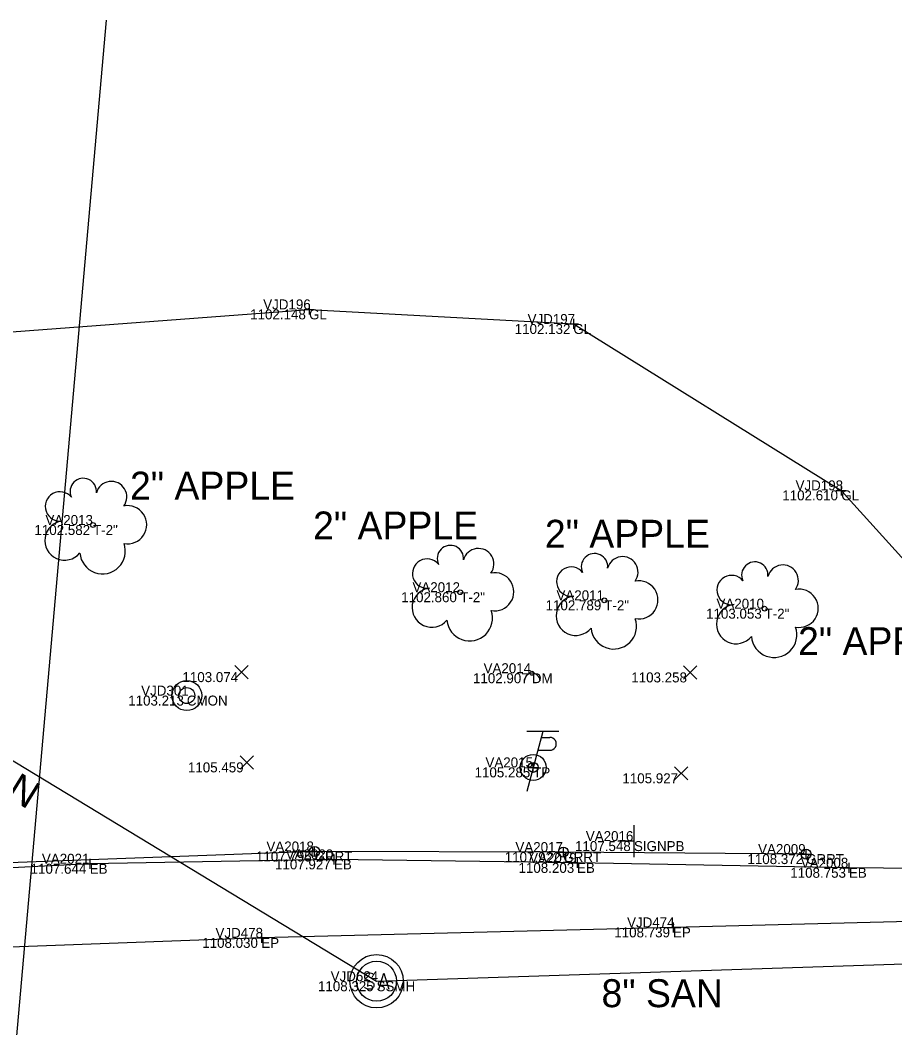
# Model space of a CAD drawing. Extents: x 1629915 to 1630675, y 484401 to 484601.
# Drawn here: x 1630337.7 to 1630425.3, y 484495.4 to 484596.3 of the extents above; entities that cross this region are included whole.
import ezdxf

# ---------------------------------------------------------------- set-up
doc = ezdxf.new("R2010")
doc.units = 0
for name, color, linetype in [('BR_X_Sub_Foot_Object', 7, 'Continuous'), ('Default', 7, 'Continuous'), ('GK_Drainage_Nodes', 7, 'Continuous'), ('PV_X_EOP', 7, 'Continuous'), ('PV_X_Shoulder_Aggregate', 7, 'Continuous'), ('RD_X_GR_Rt', 7, 'Continuous'), ('SC_Scratch2', 7, 'Continuous'), ('SN_X_Public', 7, 'Continuous'), ('SV_X_Mon_Cells_Found', 7, 'Continuous'), ('SV_X_Random_Point', 7, 'Continuous'), ('SV_X_Shot_Marker', 7, 'Continuous'), ('SV_X_Text_Comment', 7, 'Continuous'), ('SV_X_Text_Elevation', 7, 'Continuous'), ('SV_X_Text_Name', 7, 'Continuous'), ('TX_X_20', 7, 'Continuous'), ('UT_X_Gas', 7, 'Continuous'), ('UT_X_Misc_Cells', 7, 'Continuous'), ('UT_X_Sanitary_Cells', 7, 'Continuous'), ('UT_X_Sanitary_Line', 7, 'Continuous'), ('VG_X_Cells', 7, 'Continuous')]:
    doc.layers.add(name, color=color, linetype=linetype)

# ---------------------------------------------------------------- blocks, each defined once
blk = doc.blocks.new('SurveyPointCell')
at = {"layer": 'Default'}
for p, q in [((-0.5, 0), (0.5, 0)), ((0, -0.5), (0, 0.5))]:
    blk.add_line(p, q, dxfattribs=at)
blk.add_circle((0, 0), 0.5, dxfattribs=at)

msp = doc.modelspace()

# ---------------------------------------------------------------- linework, layer by layer
at = {"layer": 'BR_X_Sub_Foot_Object'}
msp.add_line((1630334.98, 484467.23), (1630346.37, 484596.32), dxfattribs=at)
at = {"layer": 'GK_Drainage_Nodes'}
for p, q in [((1630373.42, 484502.09), (1630373.42, 484502.09)), ((1630373.42, 484500.09), (1630373.42, 484500.09)), ((1630373.42, 484500.09), (1630373.42, 484500.09)), ((1630373.42, 484500.09), (1630373.42, 484500.09)), ((1630373.42, 484498.09), (1630373.42, 484498.09))]:
    msp.add_line(p, q, dxfattribs=at)
msp.add_circle((1630373.42, 484500.09), 2, dxfattribs=at)
at = {"layer": 'PV_X_EOP'}
msp.add_lwpolyline([(1630649.54, 484512.34), (1630611.09, 484510.96), (1630568.31, 484509.62), (1630527.92, 484508.55), (1630486.05, 484507.69), (1630439.97, 484506.41), (1630403.1, 484505.48), (1630361.88, 484504.43), (1630301.74, 484502.19)], dxfattribs=at)
at = {"layer": 'PV_X_Shoulder_Aggregate'}
msp.add_lwpolyline([(1630609.29, 484512.62), (1630601.38, 484512.79), (1630594.37, 484513.03), (1630564.66, 484511.71), (1630557.67, 484510.64), (1630535.06, 484510.05), (1630513.96, 484509.73), (1630489.96, 484510.39), (1630468.46, 484511.02), (1630445.09, 484511.2), (1630420.71, 484511.45), (1630393.49, 484511.94), (1630369.15, 484512.29), (1630344.7, 484511.85), (1630320.66, 484510.61), (1630304.12, 484509.44), (1630303.96, 484508.98)], dxfattribs=at)
at = {"layer": 'RD_X_GR_Rt'}
msp.add_lwpolyline([(1630416.42, 484512.82), (1630392.12, 484513.02), (1630367.21, 484513.08), (1630304.23, 484510.75)], dxfattribs=at)
at = {"layer": 'SN_X_Public'}
for p, q in [((1630399.19, 484515.72), (1630399.19, 484512.52)), ((1630399.19, 484514.12), (1630397.59, 484514.12))]:
    msp.add_line(p, q, dxfattribs=at)
at = {"layer": 'SV_X_Mon_Cells_Found'}
for radius in [1.5, 0.8]:
    msp.add_circle((1630354.42, 484528.69), radius, dxfattribs=at)
at = {"layer": 'SV_X_Random_Point'}
for p, q in [((1630359.23, 484530.37), (1630360.57, 484531.7)), ((1630359.23, 484531.7), (1630360.57, 484530.37)), ((1630404.15, 484530.34), (1630405.48, 484531.68)), ((1630404.15, 484531.68), (1630405.48, 484530.34)), ((1630359.75, 484521.33), (1630361.08, 484522.67)), ((1630359.75, 484522.67), (1630361.08, 484521.33)), ((1630403.26, 484520.24), (1630404.59, 484521.57)), ((1630403.26, 484521.57), (1630404.59, 484520.24))]:
    msp.add_line(p, q, dxfattribs=at)
at = {"layer": 'SV_X_Shot_Marker'}
for p, q in [((1630366.16, 484567.36), (1630367.16, 484567.36)), ((1630366.66, 484567.86), (1630366.66, 484566.86)), ((1630366.66, 484567.36), (1630366.66, 484567.36)), ((1630393.12, 484566.4), (1630393.12, 484565.4)), ((1630392.62, 484565.9), (1630393.62, 484565.9)), ((1630393.12, 484565.9), (1630393.12, 484565.9)), ((1630419.45, 484549.24), (1630420.45, 484549.24)), ((1630419.95, 484549.74), (1630419.95, 484548.74)), ((1630419.95, 484549.24), (1630419.95, 484549.24)), ((1630369.15, 484512.79), (1630369.15, 484511.79)), ((1630344.2, 484511.85), (1630345.2, 484511.85)), ((1630344.7, 484512.35), (1630344.7, 484511.35)), ((1630344.7, 484511.85), (1630344.7, 484511.85)), ((1630368.65, 484512.29), (1630369.65, 484512.29)), ((1630369.15, 484512.29), (1630369.15, 484512.29)), ((1630392.99, 484511.94), (1630393.99, 484511.94)), ((1630393.49, 484512.44), (1630393.49, 484511.44)), ((1630393.49, 484511.94), (1630393.49, 484511.94)), ((1630420.71, 484511.95), (1630420.71, 484510.95)), ((1630420.21, 484511.45), (1630421.21, 484511.45)), ((1630420.71, 484511.45), (1630420.71, 484511.45)), ((1630402.6, 484505.48), (1630403.6, 484505.48)), ((1630403.1, 484505.98), (1630403.1, 484504.98)), ((1630403.1, 484505.48), (1630403.1, 484505.48)), ((1630361.38, 484504.43), (1630362.38, 484504.43)), ((1630361.88, 484504.93), (1630361.88, 484503.93)), ((1630361.88, 484504.43), (1630361.88, 484504.43))]:
    msp.add_line(p, q, dxfattribs=at)
at = {"layer": 'UT_X_Gas'}
for points in [[(1630098.57, 484496.17), (1630109.66, 484497.04), (1630113.02, 484497.7), (1630113.95, 484498.76), (1630114.05, 484508.26), (1630114.56, 484509.57), (1630115.81, 484510.86), (1630129.42, 484519.99), (1630159.4, 484536.24), (1630181.58, 484547.98), (1630213.12, 484562.01), (1630240.48, 484573.33), (1630274.59, 484574.58), (1630290.01, 484572.98), (1630327.07, 484564.38), (1630366.66, 484567.36), (1630393.12, 484565.9), (1630419.95, 484549.24), (1630440.64, 484526.36), (1630450.49, 484510.25), (1630452.08, 484508.49), (1630453.28, 484508.55), (1630468.94, 484509.13)], [(1630098.57, 484496.17), (1630109.66, 484497.04), (1630113.02, 484497.7), (1630113.95, 484498.76), (1630114.05, 484508.26), (1630114.56, 484509.57), (1630115.81, 484510.86), (1630129.42, 484519.99), (1630159.4, 484536.24), (1630181.58, 484547.98), (1630213.12, 484562.01), (1630240.48, 484573.33), (1630274.59, 484574.58), (1630290.01, 484572.98), (1630327.07, 484564.38), (1630366.66, 484567.36), (1630393.12, 484565.9), (1630419.95, 484549.24), (1630440.64, 484526.36), (1630450.49, 484510.25), (1630452.08, 484508.49), (1630453.28, 484508.55), (1630494.38, 484510.08)]]:
    msp.add_lwpolyline(points, dxfattribs=at)
at = {"layer": 'UT_X_Misc_Cells'}
for p, q in [((1630390.07, 484525.1), (1630388.46, 484519.1)), ((1630391.67, 484525.1), (1630388.47, 484525.1)), ((1630389.91, 484524.5), (1630390.76, 484524.5)), ((1630389.56, 484523.22), (1630390.76, 484523.22))]:
    msp.add_line(p, q, dxfattribs=at)
for centre, radius in [((1630388.97, 484530.93), 0.2), ((1630389.1, 484521.5), 1.3)]:
    msp.add_circle(centre, radius, dxfattribs=at)
for centre, radius, start, end in [((1630389, 484530.13), 0.8, 2.2454, 182.2454), ((1630390.77, 484523.86), 0.638, 268.8767, 91.1233)]:
    msp.add_arc(centre, radius, start, end, dxfattribs=at)
at = {"layer": 'UT_X_Sanitary_Cells'}
for points in [[(1630373.09, 484500.78), (1630373.06, 484500.81), (1630373.03, 484500.83), (1630372.91, 484500.87), (1630372.77, 484500.89), (1630372.67, 484500.89), (1630372.64, 484500.89), (1630372.47, 484500.86), (1630372.33, 484500.78), (1630372.25, 484500.68), (1630372.22, 484500.58), (1630372.22, 484500.5), (1630372.25, 484500.4), (1630372.35, 484500.32), (1630373.04, 484499.94), (1630373.1, 484499.89), (1630373.13, 484499.84), (1630373.15, 484499.76), (1630373.15, 484499.69), (1630373.14, 484499.61), (1630373.13, 484499.56), (1630373.1, 484499.5), (1630373.08, 484499.45), (1630373.05, 484499.41), (1630373.01, 484499.37), (1630372.98, 484499.35), (1630372.93, 484499.32), (1630372.89, 484499.31), (1630372.77, 484499.29), (1630372.6, 484499.29), (1630372.48, 484499.32), (1630372.32, 484499.41), (1630372.22, 484499.48)], [(1630373.63, 484499.29), (1630374.13, 484500.89), (1630374.63, 484499.29)], [(1630374.5, 484499.67), (1630373.76, 484499.67)]]:
    msp.add_lwpolyline(points, dxfattribs=at)
for radius in [2.67, 2]:
    msp.add_circle((1630373.42, 484500.09), radius, dxfattribs=at)
at = {"layer": 'UT_X_Sanitary_Line'}
msp.add_lwpolyline([(1629930.75, 484483.73), (1630048.13, 484488.31), (1630252.72, 484494.6), (1630261.76, 484567.79), (1630373.42, 484500.09), (1630654.86, 484509.35)], dxfattribs=at)
at = {"layer": 'VG_X_Cells'}
for centre in [(1630345.03, 484545.77), (1630381.79, 484539.04), (1630396.22, 484538.23), (1630412.27, 484537.39)]:
    msp.add_circle(centre, 0.24, dxfattribs=at)
for centre, radius, start, end in [((1630344.05, 484549.13), 1.32, 354.0047, 205.9741), ((1630346.86, 484548.59), 1.55, 323.83, 165.0376), ((1630341.72, 484547.63), 1.47, 39.0625, 279.5412), ((1630348.49, 484545.8), 1.91, 259.1453, 101.4596), ((1630342.18, 484544.22), 1.97, 96.1722, 320.5737), ((1630345.98, 484543.16), 2.28, 184.9476, 19.4572), ((1630380.81, 484542.41), 1.32, 354.0047, 205.9741), ((1630383.62, 484541.87), 1.55, 323.83, 165.0376), ((1630395.24, 484541.6), 1.32, 354.0047, 205.9741), ((1630378.48, 484540.91), 1.47, 39.0625, 279.5412), ((1630398.05, 484541.06), 1.55, 323.83, 165.0376), ((1630411.29, 484540.76), 1.32, 354.0047, 205.9741), ((1630414.1, 484540.22), 1.55, 323.83, 165.0376), ((1630385.25, 484539.08), 1.91, 259.1453, 101.4596), ((1630392.91, 484540.1), 1.47, 39.0625, 279.5412), ((1630399.68, 484538.27), 1.91, 259.1453, 101.4596), ((1630408.96, 484539.26), 1.47, 39.0625, 279.5412), ((1630378.94, 484537.5), 1.97, 96.1722, 320.5737), ((1630415.73, 484537.43), 1.91, 259.1453, 101.4596), ((1630393.37, 484536.68), 1.97, 96.1722, 320.5737), ((1630409.42, 484535.85), 1.97, 96.1722, 320.5737), ((1630382.74, 484536.44), 2.28, 184.9476, 19.4572), ((1630397.17, 484535.63), 2.28, 184.9476, 19.4572), ((1630413.22, 484534.79), 2.28, 184.9476, 19.4572)]:
    msp.add_arc(centre, radius, start, end, dxfattribs=at)

# ---------------------------------------------------------------- block references
at = {"layer": 'SC_Scratch2'}
for p in [(1630389.1, 484521.5), (1630367.21, 484513.08), (1630392.12, 484513.02), (1630416.42, 484512.82)]:
    msp.add_blockref('SurveyPointCell', p, dxfattribs=at)

# ---------------------------------------------------------------- texts
at = {"layer": 'SV_X_Text_Comment'}
for s, p in [('GL', (1630366.66, 484566.36)), ('GL', (1630393.12, 484564.9)), ('GL', (1630419.95, 484548.24)), ('T-2"', (1630345.03, 484544.77)), ('T-2"', (1630381.79, 484538.04)), ('T-2"', (1630396.22, 484537.23)), ('T-2"', (1630412.27, 484536.39)), ('DM', (1630388.97, 484529.93)), ('CMON', (1630354.42, 484527.69)), ('TP', (1630389.1, 484520.5)), ('SIGNPB', (1630399.19, 484513.12)), ('GRRT', (1630367.21, 484512.08)), ('GRRT', (1630392.12, 484512.02)), ('GRRT', (1630416.42, 484511.82)), ('EB', (1630344.7, 484510.85)), ('EB', (1630369.15, 484511.29)), ('EB', (1630393.49, 484510.94)), ('EB', (1630420.71, 484510.45)), ('EP', (1630403.1, 484504.48)), ('EP', (1630361.88, 484503.43)), ('SSMH', (1630373.42, 484499.09))]:
    msp.add_text(s, height=1, dxfattribs=at).set_placement(p)
at = {"layer": 'SV_X_Text_Elevation'}
for s, p in [('1102.148', (1630360.76, 484566.36)), ('1102.132', (1630387.25, 484564.9)), ('1102.610', (1630414.04, 484548.24)), ('1102.582', (1630339.16, 484544.77)), ('1102.860', (1630375.88, 484538.04)), ('1102.789', (1630390.34, 484537.23)), ('1103.053', (1630406.41, 484536.39)), ('1103.074', (1630353.98, 484530.04)), ('1102.907', (1630383.07, 484529.93)), ('1103.258', (1630398.92, 484530.01)), ('1103.213', (1630348.55, 484527.69)), ('1105.459', (1630354.53, 484521)), ('1105.285', (1630383.23, 484520.5)), ('1105.927', (1630398.03, 484519.91)), ('1107.548', (1630393.29, 484513.12)), ('1107.795', (1630361.34, 484512.08)), ('1107.922', (1630386.25, 484512.02)), ('1108.372', (1630410.55, 484511.82)), ('1107.644', (1630338.78, 484510.85)), ('1107.927', (1630363.25, 484511.29)), ('1108.203', (1630387.63, 484510.94)), ('1108.753', (1630414.84, 484510.45)), ('1108.739', (1630397.22, 484504.48)), ('1108.030', (1630355.96, 484503.43)), ('1108.325', (1630367.55, 484499.09))]:
    msp.add_text(s, height=1, dxfattribs=at).set_placement(p)
at = {"layer": 'SV_X_Text_Name'}
for s, p in [('VJD196', (1630362.07, 484567.36)), ('VJD197', (1630388.54, 484565.9)), ('VJD198', (1630415.37, 484549.24)), ('VA2013', (1630340.26, 484545.77)), ('VA2012', (1630377.01, 484539.04)), ('VA2011', (1630391.43, 484538.23)), ('VA2010', (1630407.45, 484537.39)), ('VA2014', (1630384.13, 484530.93)), ('VJD301', (1630349.85, 484528.69)), ('VA2015', (1630384.32, 484521.5)), ('VA2016', (1630394.37, 484514.12)), ('VA2018', (1630362.39, 484513.08)), ('VA2017', (1630387.32, 484513.02)), ('VA2009', (1630411.62, 484512.82)), ('VA2021', (1630339.91, 484511.85)), ('VA2020', (1630364.32, 484512.29)), ('VA2019', (1630388.7, 484511.94)), ('VA2008', (1630415.89, 484511.45)), ('VJD474', (1630398.5, 484505.48)), ('VJD478', (1630357.29, 484504.43)), ('VJD624', (1630368.82, 484500.09))]:
    msp.add_text(s, height=1, dxfattribs=at).set_placement(p)
at = {"layer": 'TX_X_20'}
for s, p in [('2" APPLE', (1630348.73, 484548.31)), ('2" APPLE', (1630367.06, 484544.32)), ('2" APPLE', (1630390.27, 484543.49)), ('2" APPLE', (1630415.62, 484532.74)), ('8" SAN', (1630395.94, 484497.49))]:
    msp.add_text(s, height=2.8, dxfattribs=at).set_placement(p)
msp.add_text('8" SAN', height=2.8, rotation=328.1116, dxfattribs=at).set_placement((1630328.18, 484523.68))

doc.saveas('drawing.dxf')
